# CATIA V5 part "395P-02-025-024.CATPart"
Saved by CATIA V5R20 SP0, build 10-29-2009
Part number: 395P-02-025-024
Source: Unknown
Property "ARTICLENO": "395P-02-025-024"
Property "BOMINFO": "395P-02-025-024"
Property "CODE": "395P-02-025-024"
Property "D": "25.000"
Property "D1": "19.000"
Property "L": "78.000"
Property "L1": "38.000"
Property "L2": "8.000"
Property "L3": "25.000"
Property "L4": "4.000"
Property "LINA": "395P-02-025-024"
Property "M": "24.000"
Property "MAXLOAD": "1000 Kg"
Property "MDW": "2000 Kg"
Property "NB": "395P-02-025-024"
Property "NBSYN": "$CODE."
Property "NN": "395P"
Property "NT": "VDI 3366 Lifting Pins"
Property "R": "6.000"
Property "R1": "10.000"
Property "SUPPLIER": "CF"
Property "SW": "36.000"
Bounding box of the stored display mesh (mm): x -18 to 18, y -38 to 40, z -20.785 to 20.785
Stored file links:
  C:\Users\Utente\Desktop\3D files 395P\395P-02-025-024.CATPart
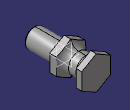
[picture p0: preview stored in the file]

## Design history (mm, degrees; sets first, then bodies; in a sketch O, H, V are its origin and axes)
Body1 "Geometry.1" (main body)
  Solid1 "395P-02-025-024.catpart": solid without history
